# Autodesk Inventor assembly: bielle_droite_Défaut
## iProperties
Shininess: 64.0
Length Units: 11269
Angle Units: 11279
Time Units: 11290
Mass Units: 11283
Length Display Precision: 3
Angle Display Precision: 2
Compacted: True
Created: 2006-01
Part Number: bielle_droite_Défaut
Document SubType Name: Assembly
Designer: riri
Density: 0.0
Volumn: 0.0
Area: 0.0
PropertySet Name: Model Information
Control State: 0
Master: False
Checked Out: False
Author: riri
